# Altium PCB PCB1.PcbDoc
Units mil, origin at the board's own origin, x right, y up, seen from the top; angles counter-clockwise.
Board outline 6000 x 4000 mil, 2 copper layers (Top Layer, Bottom Layer); 25 components, 33 nets, 145 pads, 18 vias.
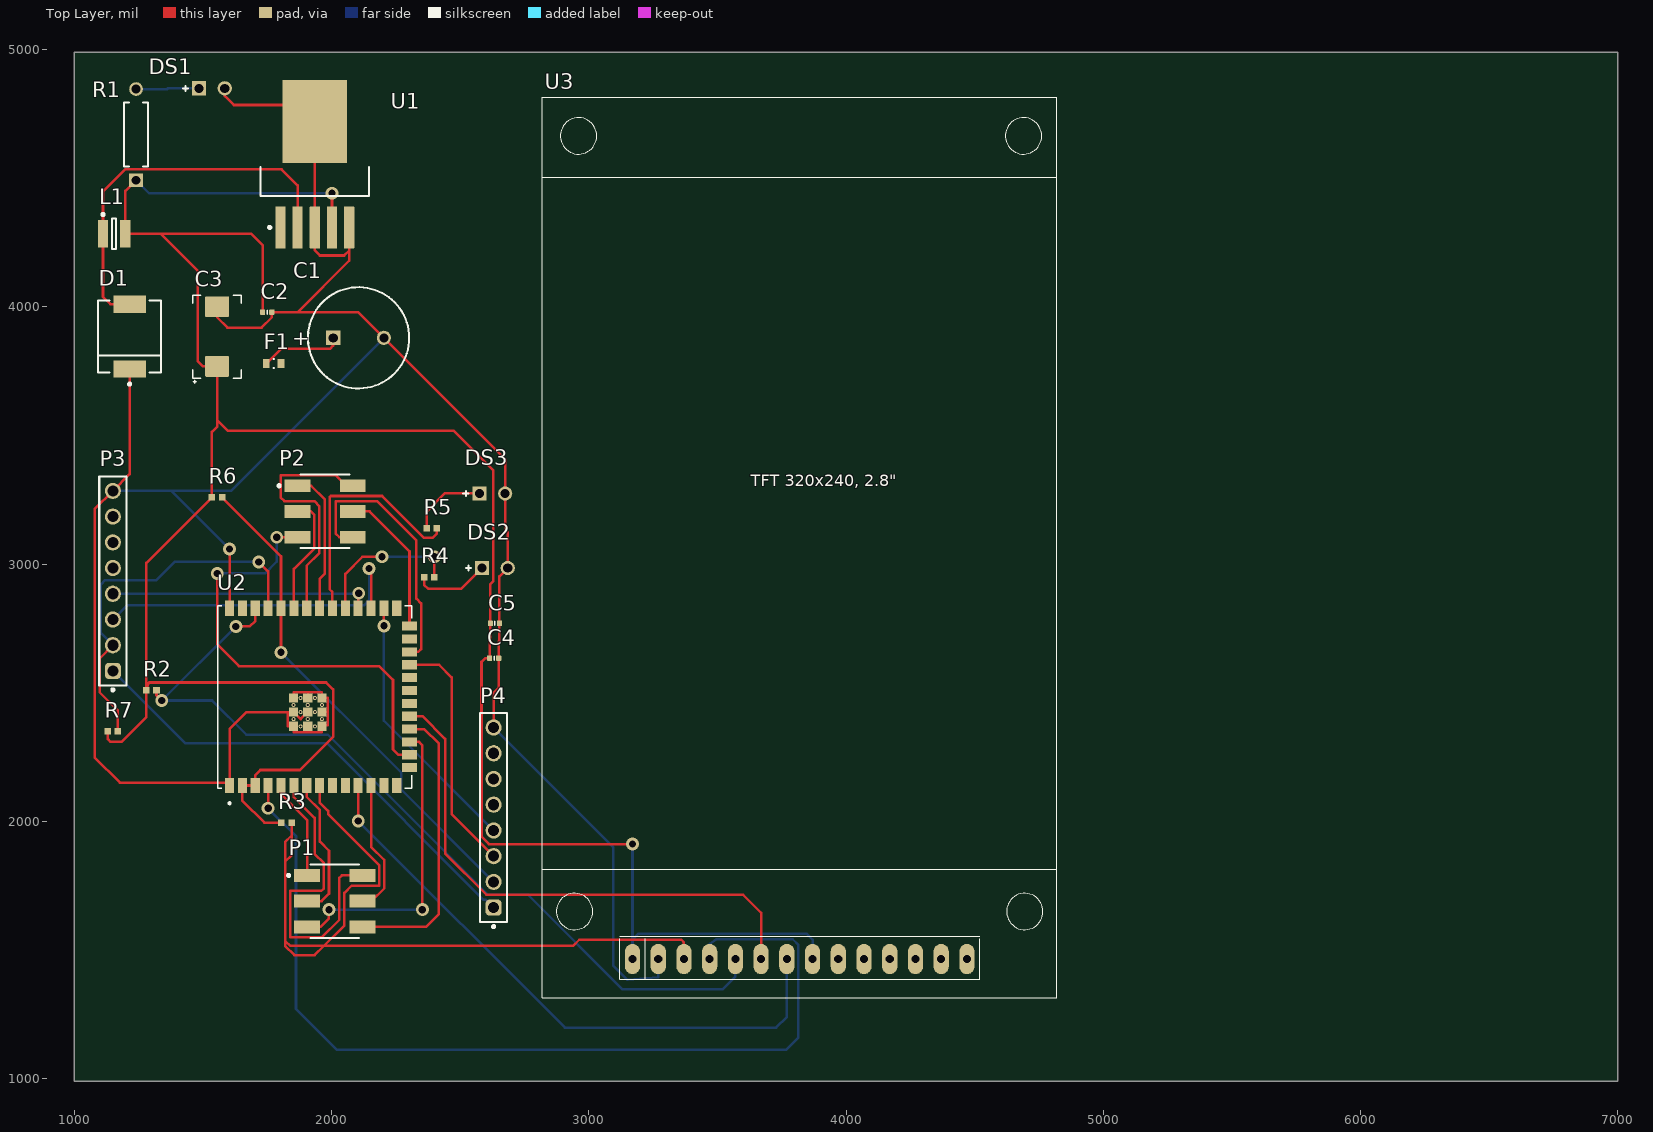
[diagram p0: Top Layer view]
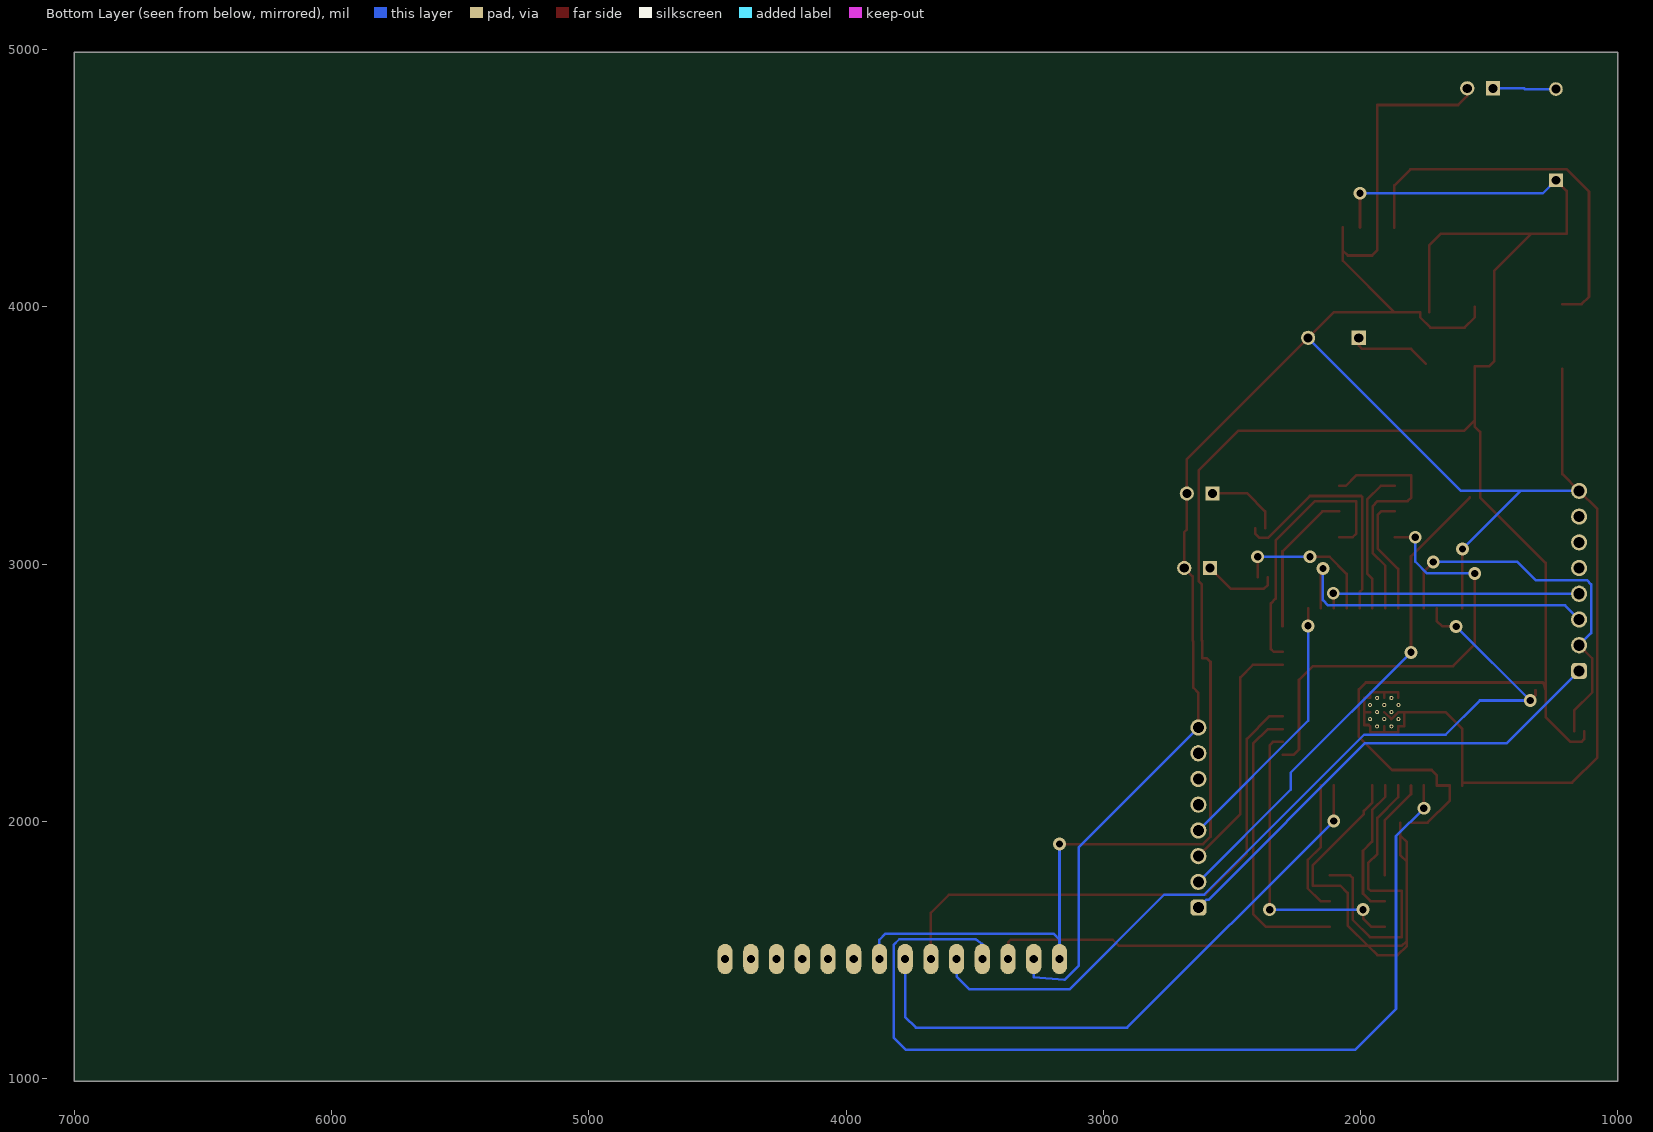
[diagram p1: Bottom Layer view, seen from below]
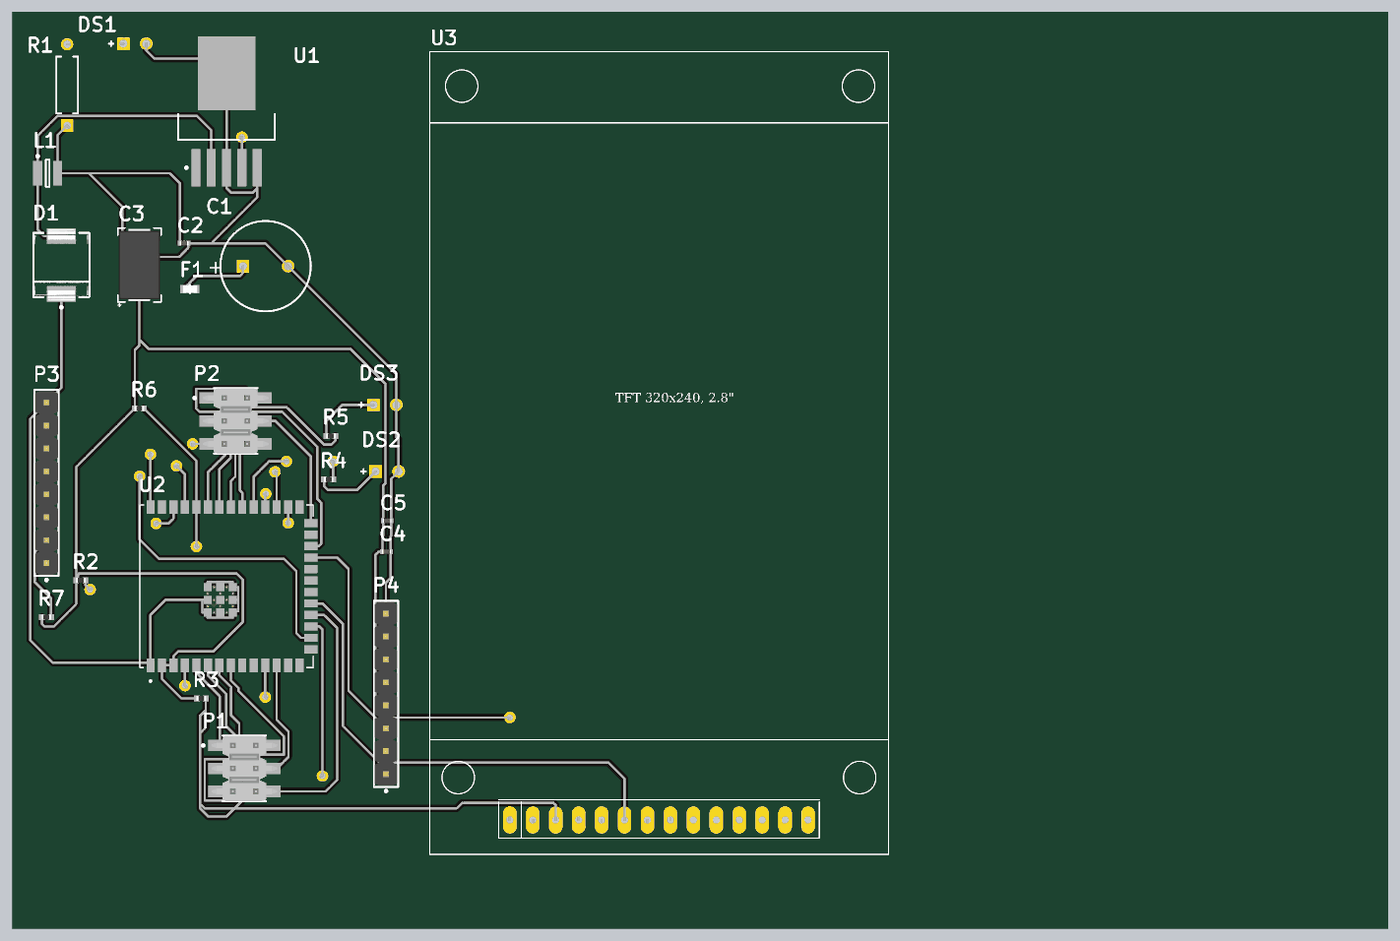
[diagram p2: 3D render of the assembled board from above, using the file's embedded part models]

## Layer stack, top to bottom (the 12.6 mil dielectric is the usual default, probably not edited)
Top Solder: solder mask 0.4, Solder Resist, Dk 3.5
Top Layer: signal copper 1.4
Dielectric 1: dielectric 12.6, FR-4, Dk 4.8
Bottom Layer: signal copper 1.4
Bottom Solder: solder mask 0.4, Solder Resist, Dk 3.5

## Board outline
1000,990 7000,990 7000,4990 1000,4990

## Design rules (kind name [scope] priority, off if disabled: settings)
Clearance [All] p1: gap=0 ignorepadtopadclearanceinfootprint=FALSE
MinimumSolderMaskSliver [All] p1: minsoldermaskwidth=0
PolygonConnect [All] p1: connectstyle=Relief reliefconductorwidth=10 reliefentries=4 polygonreliefangle="90 Angle" airgapwidth=10
RoutingVias [All] p1: holewidth=28 width=50 viastyle="Through Hole" minholewidth=28 minwidth=50 maxholewidth=28 maxwidth=50
SilkToSolderMaskClearance [IsPad] p1: minsilkscreentomaskgap=0 clearancetoexposedcopper=TRUE
SolderMaskExpansion [All] p1: expansion=0 istentingtop=FALSE
SupplyNets "Schematic Supply Nets_3" [InNet('+3.3')] p1: voltage=0.000
SupplyNets "Schematic Supply Nets_2" [InNet('+3.3V')] p2: voltage=0.000
SupplyNets "Schematic Supply Nets_1" [InNet('+9 V')] p3: voltage=0.000
SupplyNets "Schematic Supply Nets" [InNet('GND')] p4: voltage=0.000
Width [All] p1: maxlimit=10 minlimit=10 preferedwidth=10
28 further rules are at their usual default settings.

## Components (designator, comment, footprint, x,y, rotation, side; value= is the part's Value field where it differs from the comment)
C1 "ECA-1HM471" CAPPR65-500-2000X1000X2200 2105,3880 r0 top value=470µF
C2 "Capacitor 100nF +/-20% 10V 0402" CAPC0402(1005)60_L 1750,3980 r0 top value=100nF
C3 "Capacitor 330µF +/-20% 6.3V D3" PNSC-6TPF220M5L 1555,3885 r90 top value=330µF
C4 "Capacitor 100nF +/-20% 10V 0402" CAPC0402(1005)60_L 2632.28,2635 r0 top value=100nF
C5 "Capacitor 100nF +/-20% 10V 0402" CAPC0402(1005)60_L 2635,2770 r0 top value=100nF
D1 "SS34-E3/57T" FP-95402-MFG 1215,3885 r90 top
DS1 "LTL-1CHG" LTST-LTL-1CHG-2 1535,4850 r0 top
DS2 "LTL-1CHG" LTST-LTL-1CHG-2 2635,2985 r0 top
DS3 "LTL-1CHG" LTST-LTL-1CHG-2 2625,3275 r0 top
F1 "SF-0603S050-2" FP-SF-0603S-MFG 1775,3780 r0 top value=232mΩ
L1 "330uH" BOUR-SRN3015-2_V 1155,4285 r0 top
P1 "95278-101A06LF" AMPM-95278-101A06LF_V 2012.52,1690 r270 top
P2 "95278-101A06LF" AMPM-95278-101A06LF_V 1975,3205 r270 top
P3 "DOWNSTREAM" 61300811121 1150,2935 r90 top
P4 "UPSTREAM" 61300811121 2630,2015 r90 top
R1 "MFR-25FBF52-1K" RESA60-630X240 1240,4670 r90 top value=1k
R2 "Resistor 10k +/-1% 0402 63 mW" RESC1005X40X25ML05T05 1300,2510 r0 top value=10k
R3 "Resistor 10k +/-1% 0402 63 mW" RESC1005X40X25ML05T05 1825,1995 r0 top value=10k
R4 "Resistor 10k +/-1% 0402 63 mW" RESC1005X40X25ML05T05 2380,2950 r0 top value=10k
R5 "Resistor 10k +/-1% 0402 63 mW" RESC1005X40X25ML05T05 2390,3140 r0 top value=10k
R6 "Resistor 10k +/-1% 0402 63 mW" RESC1005X40X25ML05T05 1554.68,3260 r0 top value=10k
R7 "Resistor 10k +/-1% 0402 63 mW" RESC1005X40X25ML05T05 1150,2350 r0 top value=10k
U1 "LM2596S-3.3" KTT0005B_N 1935,4555 r90 top
U2 "ESP32-S3-WROOM-1-N4" XCVR_ESP32-S3-WROOM-1U-N4 1934.73,2484.06 r90 top
U3 "TFT_320x240" PCBComponent_1 3970,2545 r0 top

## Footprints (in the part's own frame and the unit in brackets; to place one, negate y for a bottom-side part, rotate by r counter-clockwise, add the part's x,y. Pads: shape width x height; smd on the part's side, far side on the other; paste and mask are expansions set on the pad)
61300811121 [mm] "Pin Header, pitch 2.54 mm, THT, Vertical, single row, 8p"
  rrect50% 1.6x1.6 hole 1.1: 1(-8.89,0)
  round 1.6 hole 1.1: 2(-6.35,0) 3(-3.81,0) 4(-1.27,0) 5(1.27,0) 6(3.81,0) 7(6.35,0) 8(8.89,0)
  silkscreen extent -10.88,-1.34 10.31,1.34, body extent -10.16,-1.27 10.16,1.27, height 8.57
AMPM-95278-101A06LF_V [mm] "SMD, 6-Leads, Body 7.26x4.83mm, Pitch 2.54mm"
  rect 1.27x2.54 smd: 1(-2.54,-2.73) 2(-2.54,2.73) 3(0,-2.73) 4(0,2.73) 5(2.54,-2.73) 6(2.54,2.73)
  silkscreen extent -3.63,-4.67 3.63,2.41, body extent -3.61,-3.64 3.61,3.64, height 9.71
BOUR-SRN3015-2_V [mm] "SMD, 2-Leads, Body 3x3mm, Height 1.5mm"
  rect 1x2.7 smd: 1(-1.1,0) 2(1.1,0)
  silkscreen extent -1.22,-1.5 0.2,2.02, body extent -1.5,-1.5 1.5,1.5, height 1.5
CAPC0402(1005)60_L [mm] "Chip Capacitor, Body 1.0x0.5mm, Height 0.6mm, IPC High Density"
  rrect25% 0.5x0.55 smd: 1(-0.45,0) 2(0.45,0)
  silkscreen extent 0,-0.2 0,0.2, body extent -0.5,-0.25 0.5,0.25, height 0.6
CAPPR65-500-2000X1000X2200 [mm] "THD, 2-Leads, Dia 10mm, Pin Spacing 5mm"
  rect 1.4x1.4 hole 0.9: 1(-2.5,0)
  round 1.4 hole 0.9: 2(2.5,0)
  silkscreen extent -5,-5 5,5, body extent -5,-5 4.95,5, height 22
FP-95402-MFG [mm]
  rect 1.72x3.2 smd paste+0 mask+0: 1(-3.205,0) 2(3.205,0)
  silkscreen extent -4.82,-3.11 3.55,3.11, body extent -4.17,-3.21 4.17,3.21, height 0.25
FP-SF-0603S-MFG [mm]
  rect 0.65x0.9 smd paste+0 mask+0: 1(-0.725,0) 2(0.725,0)
  silkscreen extent -0.02,-0.45 0.02,0.45, body extent -1.15,-0.55 1.15,0.55, height 0.25
KTT0005B_N [mm] "DPAK, 5-Leads, Body 10.65x9.65mm, Pitch 1.7mm, IPC Medium Density"
  rrect10% 4.15x1 smd: 1(-6.25,3.4) 2(-6.25,1.7) 3(-6.25,0) 4(-6.25,-1.7) 5(-6.25,-3.4)
  rrect2% 8.2x6.4 smd: 6(4.2,0)
  silkscreen extent -6.37,-5.35 -0.3,5.35, body extent -3.15,-5.32 6.5,5.33, height 4.83
LTST-LTL-1CHG-2 [mm] "TH, 2-Leads, Dia 3.8mm"
  rect 1.4x1.4 hole 0.9: 1(-1.27,0)
  round 1.4 hole 0.9: 2(1.27,0)
  silkscreen extent -2.87,-0.25 -2.37,0.25, body extent -1.9,-1.9 1.9,1.9, height 6.5
PCBComponent_1 [mm]
  rrect100% 1.5x3 hole 0.8: 1(-20.32,-27.432) 2(-17.78,-27.432) 3(-15.24,-27.432) 4(-12.7,-27.432) 5(-10.16,-27.432) 6(-7.62,-27.432) 7(-5.08,-27.432) 8(-2.54,-27.432) 9(0,-27.432) 10(2.54,-27.432) 11(5.08,-27.432) 12(7.62,-27.432) 13(10.16,-27.432) 14(12.7,-27.432)
  silkscreen extent -29.21,-31.24 21.59,57.66
PNSC-6TPF220M5L [mm] "Molded Capacitor, 2-Leads, Body 7.60x4.60mm, IPC High Density"
  rrect10% 2.05x2.35 smd: 1(-2.95,0) 2(2.95,0)
  silkscreen extent -4.6,-2.4 4.1,2.4, body extent -4.02,-2.3 4.02,2.3, height 3
RESA60-630X240 [mm] "Axial Resistor, 2-Leads, Dia 2.4mm, Body Length 6.3mm"
  rect 1.35x1.35 hole 0.85: 1(-4.5,0)
  round 1.35 hole 0.85: 2(4.5,0)
  silkscreen extent -3.15,-1.2 3.15,1.2, body extent -4.77,-1.19 4.77,1.2, height 2.4
RESC1005X40X25ML05T05 [mm] "Chip Resistor, 2-Leads, Body 1.05x0.55mm, IPC Low Density"
  rect 0.65x0.65 smd: 1(-0.5,0) 2(0.5,0)
  body extent -0.53,-0.28 0.53,0.28, height 0.4
XCVR_ESP32-S3-WROOM-1U-N4 [mm]
  rect 1.5x0.9 smd: 1(-8.75,8.41) 2(-8.75,7.14) 3(-8.75,5.87) 4(-8.75,4.6) 5(-8.75,3.33) 6(-8.75,2.06) 7(-8.75,0.79) 8(-8.75,-0.48) 9(-8.75,-1.75) 10(-8.75,-3.02) 11(-8.75,-4.29) 12(-8.75,-5.56) 13(-8.75,-6.83) 14(-8.75,-8.1) 27(8.75,-8.1) 28(8.75,-6.83) 29(8.75,-5.56) 30(8.75,-4.29) 31(8.75,-3.02) 32(8.75,-1.75) 33(8.75,-0.48) 34(8.75,0.79) 35(8.75,2.06) 36(8.75,3.33) 37(8.75,4.6) 38(8.75,5.87) 39(8.75,7.14) 40(8.75,8.41)
  rect 0.9x1.5 smd: 15(-6.985,-9.35) 16(-5.715,-9.35) 17(-4.445,-9.35) 18(-3.175,-9.35) 19(-1.905,-9.35) 20(-0.635,-9.35) 21(0.635,-9.35) 22(1.905,-9.35) 23(3.175,-9.35) 24(4.445,-9.35) 25(5.715,-9.35) 26(6.985,-9.35)
  rect 0.9x0.9 smd: 41_1(-2.9,2.09) 41_2(-1.5,2.09) 41_3(-0.1,2.09) 41_4(-2.9,0.69) 41_5(-1.5,0.69) 41_6(-0.1,0.69) 41_7(-2.9,-0.71) 41_8(-1.5,-0.71) 41_9(-0.1,-0.71)
  round 0.4 hole 0.2 mask+0: 41_10(-2.2,2.09) 41_11(-0.8,2.09) 41_12(-2.9,1.39) 41_13(-1.5,1.39) 41_14(-0.1,1.39) 41_15(-2.2,0.69) 41_16(-0.8,0.69) 41_17(-2.9,-0.01) 41_18(-1.5,-0.01) 41_19(-0.1,-0.01) 41_20(-2.2,-0.71) 41_21(-0.8,-0.71)
  silkscreen extent -10.6,-9.6 9,9.6

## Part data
C1: library part CMP-001-00032-8, "Aluminum Electrolytic Capacitor, 470 uF, +/- 20%, 50 V, -40 to 85 degC, 2-Pin THD, RoHS, Bulk", Capacitor Type=Electrolytic, Case/Package=Radial, Manufacturer=Panasonic, Max Operating Temperature=85°C, Min Operating Temperature=-40°C, Package Description="2-Pin Radial Lead, Dia 10 mm, Height 22 mm", Package Quantity=200, Package Reference=CAPPR65-500-2000X1000X2200, Ripple Current=650mA, Tolerance=20%, Voltage Rating=50V
C2 C4 C5: library part CMP-001-00061-3, "Chip Capacitor, 100nF +/-20%, 10V, 0402, Thickness 0.6 mm", Case/Package=0402, Max Operating Temperature=85°C, Min Operating Temperature=-55°C, Tolerance=20%, Voltage Rating=10V
C3: library part CMP-001-00058-3, "Molded Tantalum Polymer Capacitor, 330 uF, +/- 20%, 6.3 V, -55 to 105 degC, 2-Pin SMD, RoHS, Tape and Reel", Case/Package=1210, Max Operating Temperature=105°C, Min Operating Temperature=-55°C, Tolerance=20%, Voltage Rating=6.3V
D1: library part CMP-02539-000012-1, "DIODE SCHOTTKY 40V 3A DO214AB", Forward Current=3A, Manufacturer=Vishay, Max Junction Temp=+150°C, Max Repetitive Reverse Voltage=40V, Max Surge Forward Current=100A, Package=95402, Peak Reverse Current=0.5mA, Temperature="-55°C to +150°C", Temperature Range Low=-55°C
DS1 DS2 DS3: library part CMP-007-00019-2, "LED Uni-Color Green, 100 mW, 30 mA, -55 to 100 degC, 2-Pin THD, RoHS, Bulk", Case/Package=Radial, Colour=Green, Forward Current=30mA, Forward Voltage=2.6V, Manufacturer=Lite-On, Max Operating Temperature=100°C, Min Operating Temperature=-55°C, Package Description="2-Pin Through Hole Device, Dia 3.8 mm", Package Quantity=1000, Power=100mW
F1: library part CMP-07399-000004-1, "FUSE BOARD MNT 500MA 50VDC 0603", Fuse Current=0.5A, Fuse Interrupt Ac Current=50A, Manufacturer="Bourns Inc.", Max Fuse Ac Voltage=35V, Max Fuse Dc Voltage=50V, Package=SF-0603S, Resistance=232mΩ, Temperature="-20°C to +105°C", Temperature Range High=+105°C, Temperature Range Low=-20°C
L1: library part CMP-0007-00002-1, "Semi-shielded Power Inductor, 33 uH, +/- 20%, 0.5 A, -40 to 125 degC, 3 x 3 x 1.5 mm SMD, RoHS and Halogen Free, Tape and Reel", Inductance="33 uH", Inductance tolerance="+/- 20%", Manufacturer=Bourns, Operating Temperature="-40 to 125 degC", PartNumber=SRN3015-330M, Rated current="0.5 A", Resistance to Solder Heat="+260 degC for 10 sec."
P1 P2: library part CMP-002-00024-2, "Male Header, Pitch 2.54 mm, 2 x 3 Position, Height 14.4 mm, RoHS, Tape and Reel", Manufacturer=Amphenol, Package Description="Male Header, Pitch 2.54 mm, 2 x 3 Position, Height 14.4 mm"
P3 P4: library part CMP-1502-01076-3, Color=Black, Contact Resistance=20mΩ, Current Rating=3A, Max Operating Temperature=105°C, Min Operating Temperature=-40°C, Operating Supply Voltage=250V
R1: library part CMP-009-00048-4, "Axial Resistor, 1 KOhm, +/- 1%, 250 mW, -55 to 155 degC, 2-Pin THD, RoHS, Bulk", Case/Package=Axial, Manufacturer=Yageo, Max Operating Temperature=155°C, Min Operating Temperature=-55°C, Package Description="2-Pin Axial Lead, Dia 2.4 mm, Body Length 6.3 mm", Package Quantity=200, Package Reference=MFR-25, Power=250mW, Tolerance=1%, Voltage Rating=250V
R2 R3 R4 R5 R6 R7: library part CMP-009-00019-5, "Chip Resistor, 10 KOhm, +/- 1%, 63 mW, -55 to 155 degC, 0402 (1005 Metric)", Case/Package=0402, Max Operating Temperature=155°C, Min Operating Temperature=-55°C, Power=63mW, Tolerance=1%, Voltage Rating=50V
U1: library part CMP-0069-00276-3, "SIMPLE SWITCHER® Power Converter 150 KHz 3A Step-Down Voltage Regulator, 5-pin TO-263", Manufacturer="Texas Instruments", PackageTopMarking="NSUZXYTTE#*LM2596S*-3.3 P+", PowerWise=N
U2: Package=None

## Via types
v1: diameter 50, hole 28, Top Layer to Bottom Layer, 18 vias

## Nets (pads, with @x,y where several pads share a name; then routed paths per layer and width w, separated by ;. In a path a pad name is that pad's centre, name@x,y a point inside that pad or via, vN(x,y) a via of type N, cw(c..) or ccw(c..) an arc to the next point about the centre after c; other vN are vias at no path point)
+3.3: P3.1 P4.1 | length 1861.1
  Bottom Layer w10: P3.1 1431,2304 1982.61,2304 2591.61,1695 2600,1695 P4.1
+3.3V: C2.1 C3.1 C4.1 C5.1 L1.2 R1.1 R2.1 R3.1 R6.1 R7.1 U1.4 U2.2 U2.3 U3.1 U3.8 | length 10385.5
  Top Layer w10: R7.1 1130.32,2320 1141.32,2309 1183,2309 1280.32,2406.32 R2.1 ; R1.1 1198.31,4451.14 L1.2 1335,4285 ; C2.1 1732.28,4240 1687.28,4285 1335,4285 ; R3.1 1738.62,1995 1653.62,2080 U2.2 U2.3 1703.62,2180 1723.62,2200 1877,2200 2006,2329 2006,2513 1979,2540 1290.32,2540 R2.1 ; U1.4 v1(2001.93,4442) ; v1(3170,1912) 2612,1912 2583,1941 2583,2620 2598,2635 C4.1 2614.57,2701 2617.28,2703.72 C5.1 2617.28,2922.28 2628,2933 2628,3366 2475,3519 1596,3519 1555,3560 ; R2.1 1280.32,3005.32 R6.1 1535,3514 1555,3534 1555,3560 ; 1335,4285 1480,4140 1480,3788.86 1500,3768.86 C3.1 1555,3560
  Bottom Layer w10: R1.1 1290.83,4442 v1(2001.93,4442) ; U3.1 3170,1540 ; v1(3170,1912) 3170,1540 ; U3.8 3870,1540 3846,1564 3194,1564 3170,1540
"+9 V": C1.1 F1.1 | length 319.1
  Top Layer w10: F1.1 1803.46,3837 1993.57,3837 2006.57,3850 C1.1
CS-15: R3.2 U2.8 U3.3 | length 3288.7
  Top Layer w10: R3.2 1844.69,1944.37 ; U2.8 1953.62,2073.96 1987,2040.58 1987,2028 2185,1830 2185,1750 2078,1750 2050.04,1722.04 2050.04,1596.25 1969.79,1516 ; U3.3 3370,1530 3360,1540 2963,1540 2939,1516 1969.79,1516 ; 1820,1536 1820,1516 1856,1480 1933.79,1480 1969.79,1516 ; 1820,1536 1840,1516 1969.79,1516 ; 1820,1536 1820,1843.31 ; 1820,1843.31 1820,1919.69 1844.69,1944.37 ; 1820,1843.31 1844.69,1868 1844.69,1944.37
DC-2: R2.2 U2.38 U3.5 | length 3372.9
  Top Layer w10: R2.2 1319.69,2490.31 v1(1340,2470) ; v1(1628,2758) 1681.62,2758 1703.62,2780 U2.38
  Bottom Layer w10: v1(1628,2758) v1(1340,2470) 1536,2470 1669,2337 1986,2337 2608,1715 2763,1715 3131,1347 3520,1347 3570,1397 U3.5
"DS CTS": P3.4 U2.30 | length 1016.6
  Top Layer w10: U2.30 2103.62,2884.87 v1(2106,2887.24)
  Bottom Layer w10: P3.4 2103.76,2885 v1(2106,2887.24)
"DS RTS": P3.3 U2.29 | length 1307.7
  Top Layer w10: v1(2146,2983) 2153.62,2975.38 U2.29
  Bottom Layer w10: P3.3 1205,2840 2126,2840 2146,2860 v1(2146,2983)
GND: C1.2 C2.2 C3.2 C4.2 C5.2 D1.1 DS1.2 DS2.2 DS3.2 P3.8 P4.8 U1.3 U1.5 U1.6 U2.1 U2.40 U2.41_1 U2.41_2 U2.41_3 U2.41_4 U2.41_5 U2.41_6 U2.41_7 U2.41_8 U2.41_9 U3.2 | length 10599.1
  Top Layer w10: D1.1 1215,3350 P3.8 1079,3214 1079,2249 1177,2151 U2.1@1603.62,2151 ; C3.2 1555,3960 1595,3920 1727.72,3920 1767.72,3960 C2.2 1868.86,3980 ; DS1.2 1585,4820 1620,4785 1935,4785 U1.6 U1.3 1935,4220 1955,4200 2048.86,4200 2068.86,4220 ; U2.1 U2.1@1603.62,2151 ; U2.40 v1(1603.62,3059.38) ; U2.41_3 1852.44,2503 1907.56,2503 ; U2.41_4 1907.56,2347 ; U2.41_5 1880,2397.44 U2.41_2 1829,2425 ; U2.41_6 1907.56,2503 ; U2.41_8 1986,2425 ; U1.5 2068.86,4220 ; P4.8 2630,2500 2650,2520 C4.2 2650,2701 2652.72,2703.72 C5.2 2652.72,2952.71 DS2.2 2685,3125 2675,3135 DS3.2 2675,3408.42 C1.2 2103.43,3980 1868.86,3980 ; U2.1@1603.62,2151 1603.62,2360 1668.62,2425 1829,2425 ; 1829,2425 1829,2369.88 U2.41_1 1852.44,2347 1907.56,2347 ; 1868.86,3980 2068.86,4180 2068.86,4220 ; 1907.56,2347 1962.68,2347 U2.41_7 1967.8,2375 1986,2375 1986,2425 ; 1907.56,2503 1962.68,2503 U2.41_9 1986,2480.12 1986,2425
  Bottom Layer w10: P3.8 1378,3285 ; v1(1603.62,3059.38) 1378,3285 ; C1.2 1608.43,3285 1378,3285 ; P4.8 3095,1900 3095,1440 3151,1384 3270,1394 U3.2
Header1: P1.1 U2.5 | length 391.6
  Top Layer w10: U2.5 1803.62,2106.38 1905,2005 P1.1
Header2: P1.2 U2.6 | length 1236.9
  Top Layer w10: U2.6 1853.62,2094 1934,2013.62 1934,1874 1970.04,1837.96 1970.04,1740 1960.04,1730 1840,1730 1840,1550 1963,1550 2030.04,1617.04 2030.04,1780.04 2040,1790 P1.2
Header3: P1.3 U2.7 | length 553.4
  Top Layer w10: U2.7 1903.62,2095.67 1954.3,2045 1954.3,1921.78 1990.04,1886.04 1990.04,1719.04 1961,1690 P1.3
Header4: P1.4 U2.12 | length 526.6
  Top Layer w10: P1.4 2155,1690 2205,1740 2205,1850 2153.62,1901.38 U2.12
Header5: P1.5 U2.17 | length 1190.8
  Top Layer w10: P1.5 1958,1590 1990,1622 v1(1990,1657) ; U2.17 2340,2309.06 2353,2296.06 v1(2353,1657)
  Bottom Layer w10: v1(1990,1657) v1(2353,1657)
Header6: P1.6 U2.18 | length 1117.5
  Top Layer w10: P1.6 2367,1590 2417,1640 2417,2302.06 2360,2359.06 U2.18
Header7: P2.1 U2.33 | length 559.5
  Top Layer w10: P2.1 1921,3305 1973,3253 1973,2962.34 1953.62,2942.96 U2.33
Header8: P2.2 U2.34 | length 964.5
  Top Layer w10: U2.34 1903.62,2994.62 1953,3044 1953,3225 1933,3245 1817,3245 1802,3260 1802,3345 2017,3345 2057,3305 P2.2
Header9: P2.3 U2.35 | length 467.2
  Top Layer w10: U2.35 1853.62,2981.62 1933,3061 1933,3192 1920,3205 P2.3
Header10: P2.4 U2.26 | length 575.8
  Top Layer w10: P2.4 2148,3205 2303,3050 2303,2759.06 U2.26
Header11: P2.5 U2.16 | length 1784.2
  Top Layer w10: v1(1556,2964) 1556,2688 1640,2604 2185,2604 2239,2550 2239,2280 2259.94,2259.06 U2.16 ; v1(1787,3105) P2.5
  Bottom Layer w10: v1(1556,2964) 1741,2964 1787,3010 v1(1787,3105)
Header12: P2.6 U2.24 | length 1053.5
  Top Layer w10: P2.6 2030,3105 2017,3118 2017,3245 2177.2,3245 2330,3092.2 2330,2866 2348,2848 2348,2670 2337.06,2659.06 U2.24
MOSI-11: U2.19 U3.6 | length 2124.9
  Top Layer w10: U2.19 2354,2409.06 2442,2321.06 2442,1875 2602,1715 3600,1715 3670,1645 U3.6
NetD1_2: D1.2 L1.1 U1.2 | length 1506.1
  Top Layer w10: D1.2 1140,4011.18 1111.69,4039.49 L1.1 1111.69,4448.69 1198,4535 1806.07,4535 1868.07,4473 U1.2
NetDS1_1: DS1.1 R1.2 | length 246.2
  Bottom Layer w10: R1.2 1361,4847.17 1363.83,4850 DS1.1
NetDS2_1: DS2.1 R4.1 | length 294.9
  Top Layer w10: R4.1 2360.32,2920 2376.32,2904 2504,2904 DS2.1
NetDS3_1: DS3.1 R5.1 | length 298.9
  Top Layer w10: R5.1 2370.32,3205.32 2440,3275 DS3.1
NetR4_2: R4.2 U2.31 | length 586.6
  Top Layer w10: U2.31 2053.62,2962.62 2120,3029 v1(2196,3029) ; R4.2 v1(2399.69,3029)
  Bottom Layer w10: v1(2196,3029) v1(2399.69,3029)
NetR5_2: R5.2 U2.32 | length 950.2
  Top Layer w10: U2.32 2003.62,2892 1993,2902.62 1993,3261 1997,3265 2197,3265 2360,3102 2391.69,3102 2409.69,3120 R5.2
RST-4: U2.4 U3.4 | length 3730.1
  Top Layer w10: v1(1753.62,2051) U2.4
  Bottom Layer w10: v1(1753.62,2051) 1862,1942.62 1862,1271 2020,1113 3768,1113 3815,1160 3815,1520 3793,1542 3496,1542 3470,1524 U3.4
RX: P4.2 R6.2 U2.36 | length 1932.3
  Top Layer w10: R6.2 1803.62,3030.75 U2.36 v1(1803.62,2657.38)
  Bottom Layer w10: v1(1803.62,2657.38) 2271,2190 2271,2124 P4.2
SCK-18: U2.11 U3.7 | length 2379.7
  Top Layer w10: v1(2103.62,2001.38) U2.11
  Bottom Layer w10: v1(2103.62,2001.38) 2907,1198 3728,1198 3770,1240 U3.7
TX: P3.2 R7.2 U2.37 | length 1486.9
  Top Layer w10: P3.2 1099,2634 1099,2502 1169.69,2431.31 R7.2 ; v1(1717,3009) 1753.62,2972.38 U2.37
  Bottom Layer w10: P3.2 1103,2732 1103,2921 1120,2938 1319,2938 1390,3009 v1(1717,3009)
"US CTS": P4.4 U2.28 | length 1040.2
  Top Layer w10: v1(2203.62,2760.38) U2.28
  Bottom Layer w10: v1(2203.62,2760.38) 2203.62,2391.38 P4.4
"US RTS": P4.3 U2.23 | length 947
  Top Layer w10: U2.23 2417.94,2609.06 2467,2560 2467,2028 P4.3
pads on no net: F1.2 P3.5 P3.6 P3.7 P4.5 P4.6 P4.7 U1.1 U2.9 U2.10 U2.13 U2.14 U2.15 U2.20 U2.21 U2.22 U2.25 U2.27 U2.39 U2.41_10 U2.41_11 U2.41_12 U2.41_13 U2.41_14 U2.41_15 U2.41_16 U2.41_17 U2.41_18 U2.41_19 U2.41_20 U2.41_21 U3.9 U3.10 U3.11 U3.12 U3.13 U3.14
